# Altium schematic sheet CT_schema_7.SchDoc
size 296 x 239 mm
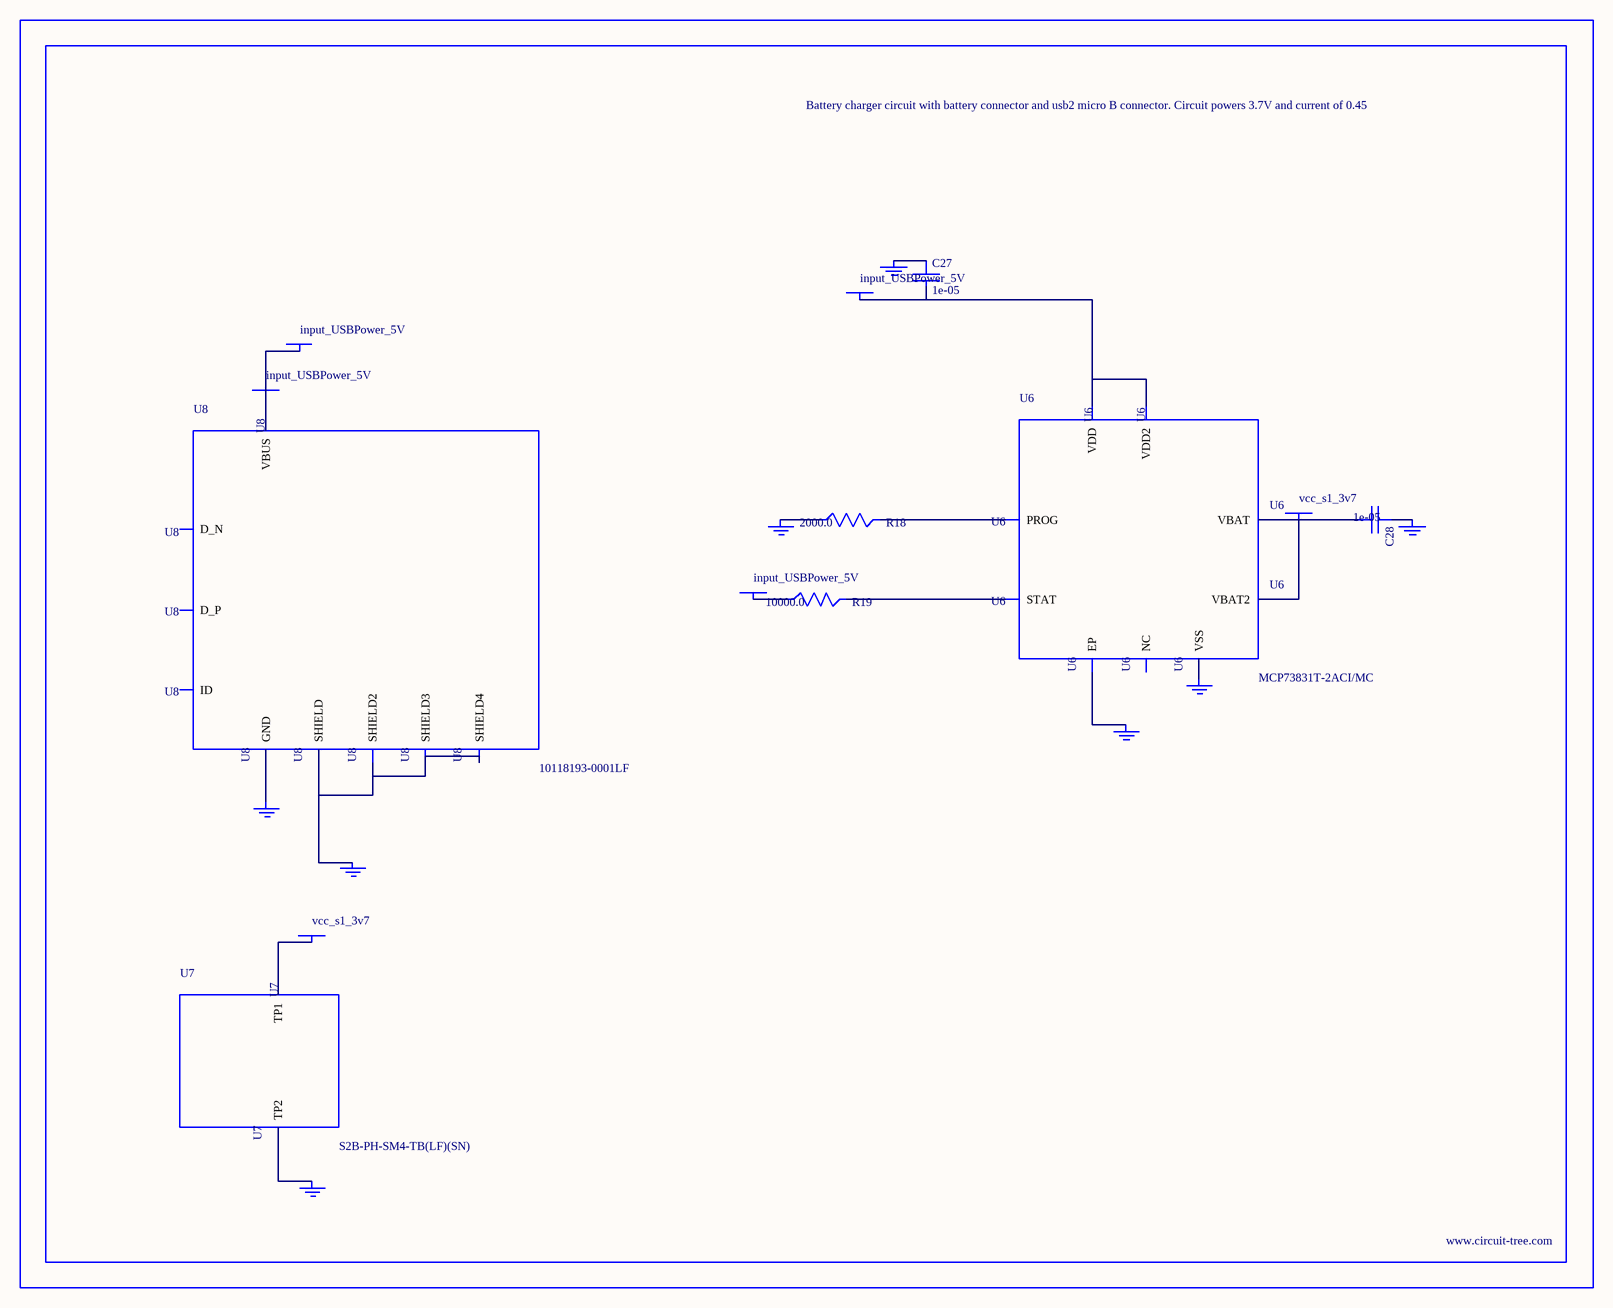
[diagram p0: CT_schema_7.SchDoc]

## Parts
BORDER6  (no value)
C27  1e-05  [C1206]
C28  1e-05  [C1206]
GND_INSTANCE_6_0  (no value)
GND_INSTANCE_6_1  (no value)
GND_INSTANCE_6_2  (no value)
GND_INSTANCE_6_3  (no value)
GND_INSTANCE_6_4  (no value)
GND_INSTANCE_6_5  (no value)
GND_INSTANCE_6_6  (no value)
GND_INSTANCE_6_7  (no value)
POWER_INSTANCE_6_0  input_USBPower_5V
POWER_INSTANCE_6_1  input_USBPower_5V
POWER_INSTANCE_6_2  vcc_s1_3v7
POWER_INSTANCE_6_3  vcc_s1_3v7
POWER_INSTANCE_6_4  input_USBPower_5V
POWER_INSTANCE_6_5  input_USBPower_5V
R18  2000.0  [R0603]
R19  10000.0  [R0603]
U6  MCP73831T-2ACI/MC  [DFN8_2X3MC]
U7  S2B-PH-SM4-TB(LF)(SN)  [JST-2-SMD]
U8  10118193-0001LF  [FCI_10118193-0001LF]

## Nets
NetC27_1: C27.1 GND_INSTANCE_6_0.0(GND)
NetC27_2: C27.2 POWER_INSTANCE_6_0.0(PWR) U6.1(VDD) U6.2(VDD2)
NetC28_1: C28.1 GND_INSTANCE_6_1.0(GND)
NetC28_2: C28.2 POWER_INSTANCE_6_2.0(PWR) U6.3(VBAT) U6.4(VBAT2)
NetGND_INSTANCE_6_2_0: GND_INSTANCE_6_2.0(GND) R18.1
NetGND_INSTANCE_6_3_0: GND_INSTANCE_6_3.0(GND) U6.9(EP)
NetGND_INSTANCE_6_4_0: GND_INSTANCE_6_4.0(GND) U6.6(VSS)
NetGND_INSTANCE_6_5_0: GND_INSTANCE_6_5.0(GND) U7.2(TP2)
NetGND_INSTANCE_6_6_0: GND_INSTANCE_6_6.0(GND) U8.6(SHIELD) U8.7(SHIELD2) U8.8(SHIELD3) U8.9(SHIELD4)
NetGND_INSTANCE_6_7_0: GND_INSTANCE_6_7.0(GND) U8.5(GND)
NetPOWER_INSTANCE_6_1_0: POWER_INSTANCE_6_1.0(PWR) R19.1
NetPOWER_INSTANCE_6_3_0: POWER_INSTANCE_6_3.0(PWR) U7.1(TP1)
NetPOWER_INSTANCE_6_4_0: POWER_INSTANCE_6_4.0(PWR) POWER_INSTANCE_6_5.0(PWR) U8.1(VBUS)
NetR18_2: R18.2 U6.8(PROG)
NetR19_2: R19.2 U6.5(STAT)

Not connected (* = marked no-connect by the designer): U6 7(NC); U8 2(D_N) 3(D_P) 4(ID)

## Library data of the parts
BORDER6 = BORDER_PAGE6
C27 C28 = C1206C106K3RACTU
GND_INSTANCE_6_0-GND_INSTANCE_6_7 = GND
POWER_INSTANCE_6_0-POWER_INSTANCE_6_5 = PWR
R18 = RC0603JR-072KL
R19 = RC0603JR-0710KL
